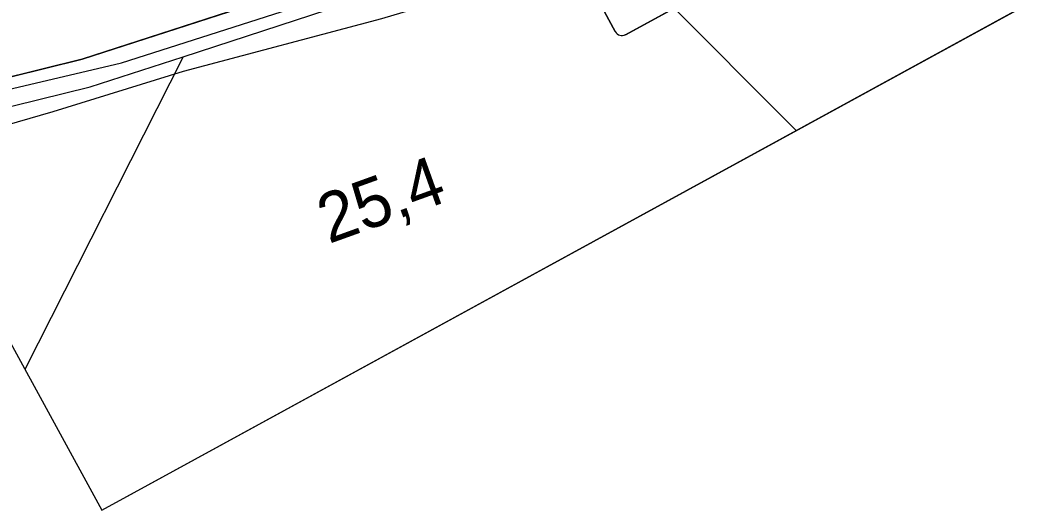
# Model space of a CAD drawing. Extents: x -9100 to -8660, y -10901 to -10569.
# Drawn here: x -9039 to -8916.9, y -10901 to -10841.1 of the extents above; entities that cross this region are included whole.
import ezdxf

# ---------------------------------------------------------------- set-up
doc = ezdxf.new("R2010")
doc.units = 0
for name, color, linetype in [('01_CETIN - sítě s NN elektropřípojky', 7, 'Continuous'), ('01_CETIN- zaměřené a kotované vnitřní STP', 7, 'Continuous'), ('04_ČEZ Distribuce - zařízení VN - nadzemní vedení', 7, 'Continuous'), ('bubliny', 7, 'Continuous'), ('HranDP', 7, 'Continuous'), ('Hranice parcel', 7, 'Continuous'), ('Rámečky-tisk', 7, 'Continuous'), ('SDĚL__BUBLINY', 7, 'Continuous'), ('Vrstva 49', 7, 'Continuous'), ('Vrstva 7', 7, 'Continuous')]:
    doc.layers.add(name, color=color, linetype=linetype)

msp = doc.modelspace()

# ---------------------------------------------------------------- linework, layer by layer
at = {"layer": '01_CETIN - sítě s NN elektropřípojky'}
msp.add_lwpolyline([(-8917.08, -10839.87), (-8942.15, -10824.25), (-8949.06, -10821.51), (-8963.57, -10829.78), (-8968.49, -10832.23), (-8975.3, -10835.1), (-8979.14, -10836.33), (-8994.81, -10841), (-9019.05, -10847.42), (-9034.97, -10852.38), (-9045.31, -10855.34), (-9052.98, -10857.16)], dxfattribs=at)
at = {"layer": '01_CETIN- zaměřené a kotované vnitřní STP'}
msp.add_lwpolyline([(-8917.08, -10839.87), (-8942.15, -10824.25), (-8949.06, -10821.51), (-8963.57, -10829.78), (-8968.49, -10832.23), (-8975.3, -10835.1), (-8979.14, -10836.33), (-8994.81, -10841), (-9019.05, -10847.42), (-9034.97, -10852.38), (-9045.31, -10855.34), (-9052.98, -10857.16)], dxfattribs=at)
at = {"layer": '04_ČEZ Distribuce - zařízení VN - nadzemní vedení'}
msp.add_line((-8973.17, -10825.46), (-8944.12, -10854.65), dxfattribs=at)
at = {"layer": 'bubliny'}
for points in [[(-8964.98, -10842.94), (-8950.45, -10835)], [(-8967.55, -10840.15), (-8966.23, -10842.57)]]:
    msp.add_lwpolyline(points, dxfattribs=at)
msp.add_arc((-8965.42, -10842.13), 0.92, 208.6505, 298.6505, dxfattribs=at)
at = {"layer": 'HranDP'}
for p, q in [((-9000.49, -10835.92), (-9031.4, -10845.93)), ((-9031.4, -10845.93), (-9053.01, -10851.26))]:
    msp.add_line(p, q, dxfattribs=at)
at = {"layer": 'Hranice parcel'}
msp.add_line((-9019.07, -10845.63), (-9038.4, -10883.84), dxfattribs=at)
for points in [[(-9055.93, -10851.76), (-9053.01, -10851.26), (-9031.4, -10845.93), (-9000.49, -10835.92), (-8982.83, -10830.76), (-8959.89, -10820.24), (-8953.3, -10812.27)], [(-9019.07, -10845.63), (-8999.46, -10839.27), (-8981.6, -10834.04), (-8957.7, -10823.09), (-8949.49, -10814.75)], [(-9052.29, -10854.69), (-9030.44, -10849.3), (-9019.07, -10845.63)]]:
    msp.add_lwpolyline(points, dxfattribs=at)
at = {"layer": 'Rámečky-tisk'}
msp.add_line((-9029.01, -10901.03), (-8844.72, -10800.34), dxfattribs=at)
for points in [[(-9100.21, -10770.71), (-9029.01, -10901.03), (-8660.43, -10699.65), (-8731.63, -10569.34)], [(-9100.21, -10770.71), (-9029.01, -10901.03), (-8844.72, -10800.34), (-8915.92, -10670.02)]]:
    msp.add_lwpolyline(points, close=True, dxfattribs=at)
msp.add_lwpolyline([(-9100.21, -10770.71), (-9029.01, -10901.03), (-9029.01, -10901.03)], dxfattribs=at)
at = {"layer": 'SDĚL__BUBLINY'}
for p, q in [((-8950.45, -10835), (-8964.98, -10842.94)), ((-8966.23, -10842.57), (-8967.55, -10840.15))]:
    msp.add_line(p, q, dxfattribs=at)
msp.add_arc((-8965.42, -10842.13), 0.92, 208.65, 298.65, dxfattribs=at)
at = {"layer": 'Vrstva 49'}
msp.add_lwpolyline([(-9055.2, -10853.1), (-9026.59, -10846.38), (-8995.2, -10836.3), (-8977.25, -10830.66), (-8958.94, -10820.43), (-8954.45, -10812.76), (-8958.4, -10809.81), (-8983.47, -10803.82), (-8986.9, -10802.53)], dxfattribs=at)

# ---------------------------------------------------------------- texts
at = {"layer": 'Vrstva 7'}
msp.add_text('25,4', height=6, rotation=19.7872, dxfattribs=at).set_placement((-9001.25, -10868.53))

doc.saveas('drawing.dxf')
